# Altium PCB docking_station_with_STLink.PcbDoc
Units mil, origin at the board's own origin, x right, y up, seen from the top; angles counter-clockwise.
Board outline 3937 x 2280 mil, 2 copper layers (Top Layer, Bottom Layer); 53 components, 48 nets, 253 pads, 82 vias.
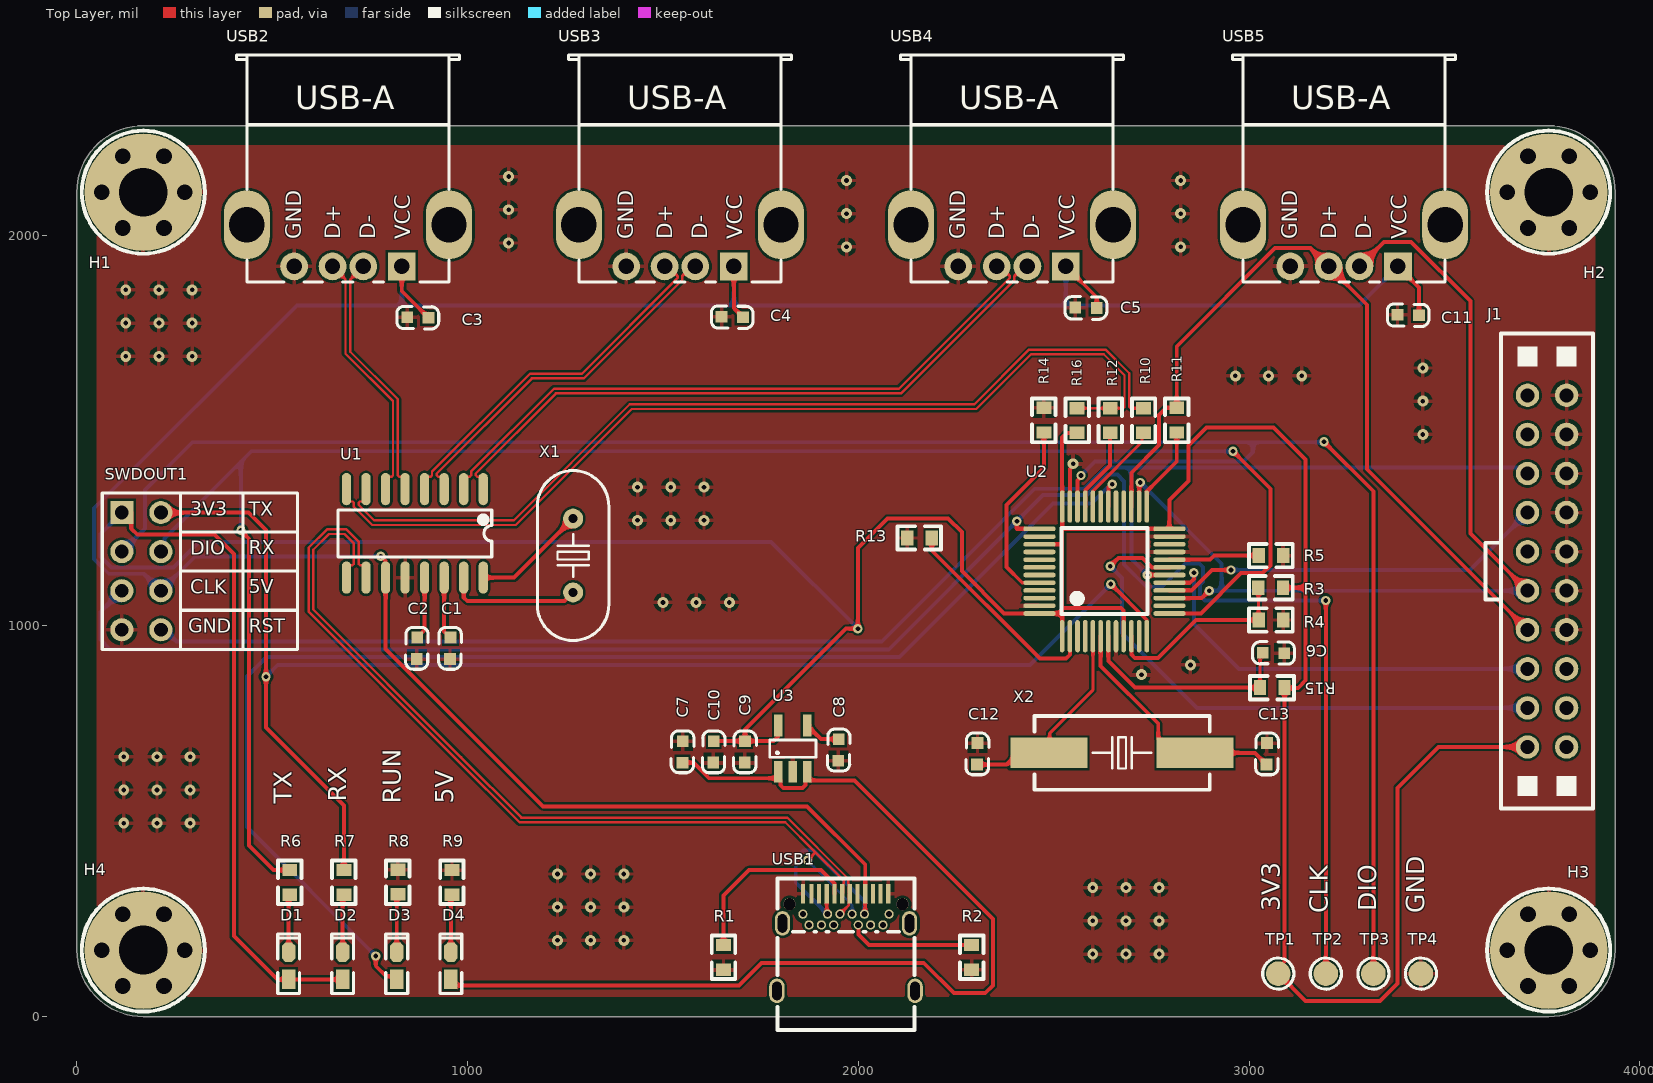
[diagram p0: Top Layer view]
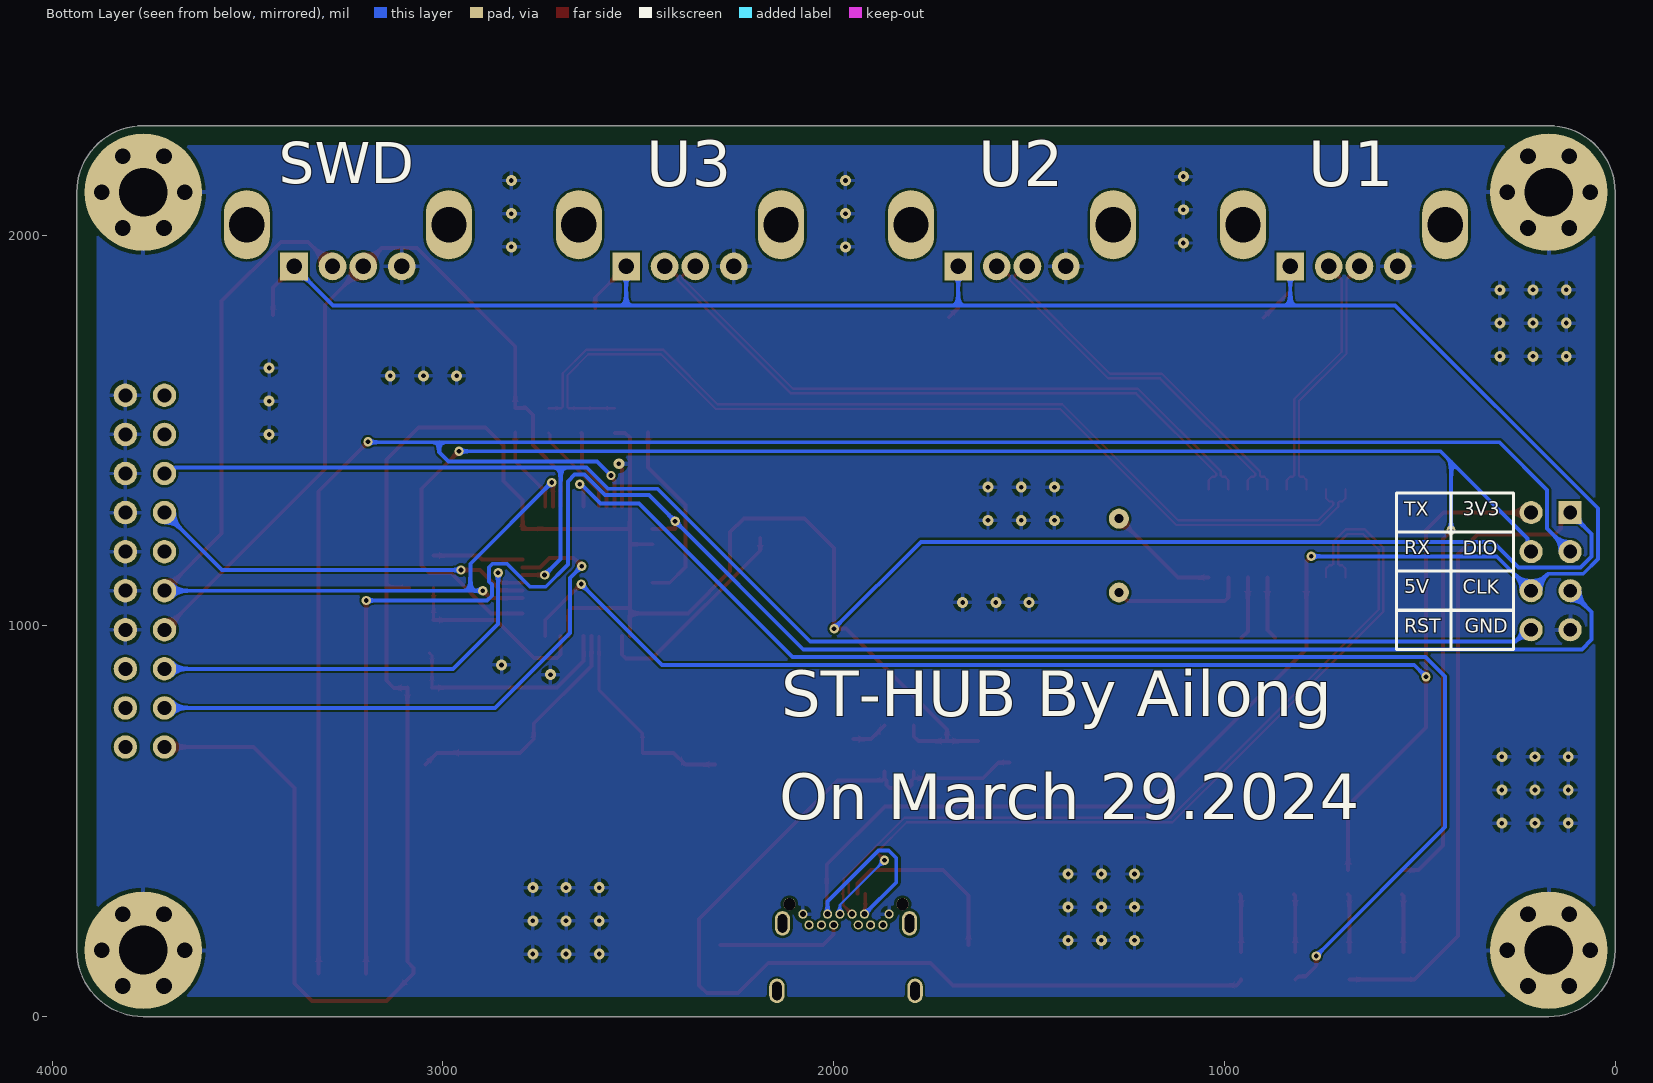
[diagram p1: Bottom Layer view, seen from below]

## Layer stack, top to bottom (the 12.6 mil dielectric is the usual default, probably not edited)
Top Solder: solder mask 0.4, Solder Resist, Dk 3.5
Top Layer: signal copper 1.4
Dielectric 1: dielectric 12.6, FR-4, Dk 4.8
Bottom Layer: signal copper 1.4
Bottom Solder: solder mask 0.4, Solder Resist, Dk 3.5

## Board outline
0,170 0,2110 cw(c170,2110) 170,2280 3767,2280 cw(c3767,2110) 3937,2110 3937,170 cw(c3767,170) 3767,0 170,0 cw(c170,170)

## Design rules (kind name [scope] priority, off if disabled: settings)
BoardOutlineClearance [All] p1: gap=10 ignorepadtopadclearanceinfootprint=FALSE except(0: Arc-SplitContinuation Track-SplitContinuation SMDPad-SplitContinuation THPad-SplitContinuation Via-SplitContinuation Fill-SplitContinuation Poly-SplitContinuation Region-SplitContinuation Text-SplitContinuation; 50: Poly-OutlineEdge)
Clearance [All] p1: gap=6 ignorepadtopadclearanceinfootprint=FALSE
DiffPairsRouting [All] p1: maxlimit=10 minlimit=6 mostfreqgap=6 toplayer_minwidth=6 toplayer_maxwidth=6 toplayer_prefwidth=6 bottomlayer_minwidth=6 bottomlayer_maxwidth=6 bottomlayer_prefwidth=6 maxuncoupledlength=500
HoleSize [All] p1: absolutevalues=TRUE maxlimit=1000 minlimit=1 maxpercent=80.000 minpercent=20.000
MinimumSolderMaskSliver [All] p1: minsoldermaskwidth=0
PolygonConnect [All] p1: connectstyle=Relief reliefconductorwidth=10 reliefentries=4 polygonreliefangle="90 Angle" airgapwidth=10
RoutingVias [All] p1: holewidth=12 width=24 viastyle="Through Hole" minholewidth=10 minwidth=20 maxholewidth=28 maxwidth=50
SilkToSolderMaskClearance [IsPad] p1: minsilkscreentomaskgap=3 clearancetoexposedcopper=TRUE
SolderMaskExpansion [All] p1: expansion=4 istentingtop=FALSE
Width [All] p1: maxlimit=50 minlimit=8 preferedwidth=10
26 further rules are at their usual default settings.

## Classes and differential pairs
differential pair class 90oum: D2 D3 D4 D_D2 D_D3 D_D4 D_UD D_USB UD USB
differential pair D_D2: +D2_N -D2_P
differential pair D_D3: +D3_N -D3_P
differential pair D_D4: +D4_N -D4_P
differential pair D_UD: +UD_N -UD_P
differential pair D_USB: +USB_N -USB_P
differential pair USB: +USB_P -USB_N
differential pair UD: +UD_P -UD_N
differential pair D4: +D4_P -D4_N
differential pair D3: +D3_P -D3_N
differential pair D2: +D2_P -D2_N

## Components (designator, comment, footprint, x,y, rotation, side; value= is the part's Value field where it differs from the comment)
C1 "10UF" 0603C 956.35,970.21 r270 top
C2 "10UF" 0603C 871.35,970.21 r270 top
C3 "100NF" 0603C 845,1790 r0 top
C4 "100NF" 0603C 1649.79,1791.35 r0 top
C5 "100NF" 0603C 2555,1815 r0 top
C6 "0.1uF" 0603C 3090.21,929.65 r180 top value=0.1u
C7 "1uF" 0603C 1551.35,705.21 r270 top
C8 "22nF" 0603C 1948.65,654.79 r90 top
C9 "10uF" 0603C 1708.65,649.85 r90 top
C10 "100nF" 0603C 1628.64,649.85 r90 top
C11 "100NF" 0603C 3379.79,1796.35 r0 top
C12 "20PF" 0603C 2303.65,644.79 r90 top
C13 "20PF" 0603C 3044.65,644.79 r90 top
D1 "color?" "LED 0603B" 542.26,130 r90 top
D2 "color?" "LED 0603B" 680.59,130 r90 top
D3 "color?" "LED 0603B" 818.92,130 r90 top
D4 "color?" "LED 0603B" 957.26,130 r90 top
H1 "固定孔" M3x4+6_N 170,2110 r0 top locked
H2 "固定孔" M3x4+6_N 3767,2110 r0 top locked
H3 "固定孔" M3x4+6_N 3767,170 r0 top locked
H4 "固定孔" M3x4+6_N 170,170 r0 top locked
J1 "JTAG" JLINK 3815,1140 r90 top locked
R1 "5.1K" 0603R 1655,182.99 r270 top value=22R
R2 "5.1K" 0603R 2290,182.99 r270 top value=22R
R3 "10K" 0603R 3087,1097.5 r180 top value=22R
R4 "10K" 0603R 3025,1015 r0 top value=22R
R5 "10K" 0603R 3025,1180 r0 top value=22R
R6 "680R" 0603R 545,375 r270 top value=22R
R7 "680R" 0603R 683.33,375 r270 top value=22R
R8 "2K" 0603R 821.67,313 r90 top value=22R
R9 "680R" 0603R 960,375 r270 top value=22R
R10 "22R" 0603R 2730,1557 r270 top
R11 "100R" 0603R 2815,1495 r90 top value=22R
R12 "22R" 0603R 2645,1557 r270 top
R13 "10K" 0603R 2125,1225 r0 top value=22R
R14 "10K" 0603R 2475,1495 r90 top value=22R
R15 "10K" 0603R 3028,841.97 r0 top value=22R
R16 "1K5" 0603R 2560,1557 r270 top value=22R
SWDOUT1 "HDR2x4_2.54" "Pin HDR2X4/2.54mm-S" 115,1290 r270 top locked
TP1 "TEST" "TEST 1.6" 3075,110 r0 top
TP2 "TEST" "TEST 1.6" 3196.67,110 r0 top
TP3 "TEST" "TEST 1.6" 3318.33,110 r0 top
TP4 "TEST" "TEST 1.6" 3440,110 r0 top
U1 "SL2.1A" SOP16 1040,1350 r270 top
U2 "STM32F103CBT6" "LQFP48 7X7" 2630,1140 r0 top
U3 "RT9193" SOT23-5 1795,626.89 r0 top
USB1 "Type-C" TYPE-C-SMD_TYPE-C-24P-QCHT 1968.5,160 r0 top locked
USB2 "USB-A" USB-A/S_A 831.46,1920 r90 top
USB3 "USB-A" USB-A/S_A 1681.35,1920 r90 top
USB4 "USB-A" USB-A/S_A 2531.24,1920 r90 top
USB5 "USB-A" USB-A/S_A 3381.13,1920 r90 top
X1 "12MHZ" "OSC HC-49S" 1270,1180 r90 top
X2 "8MHZ" "OSC HC-49SMD" 2675,675 r0 top

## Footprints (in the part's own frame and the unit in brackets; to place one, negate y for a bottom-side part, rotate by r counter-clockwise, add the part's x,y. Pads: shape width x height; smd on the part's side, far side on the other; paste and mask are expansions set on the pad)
0603C [mil]
  rect 30x30 smd: 1(0.21,-0.35) 2(55.21,-1.35)
  silkscreen extent -26,-30 81,28, body extent -1,-15 62,17, height 12
0603R [mm]
  rect 0.8x0.965 smd: 1(0,0) 2(1.6,0)
  silkscreen extent -0.64,-0.76 2.21,0.76, body extent -0.04,-0.41 1.56,0.41, height 0.45
JLINK [mil]
  round 60 hole 36 paste+0 mask+2: 1(-450,102.21) 2(-450,2.21) 3(-350,102.21) 4(-350,2.21) 5(-250,102.21) 6(-250,2.21) 7(-150,102.21) 8(-150,2.21) 9(-50,102.21) 10(-50,2.21) 11(50,102.21) 12(50,2.21) 13(150,102.21) 14(150,2.21) 15(250,102.21) 16(250,2.21) 17(350,102.21) 18(350,2.21) 19(450,102.21) 20(450,2.21)
  silkscreen extent -608,-66 608,210
"LED 0603B" [mil] "蓝色0603LED"
  rect 50x35 smd: 1(-35,0.26)
  oct 50x35 smd: 2(35,0.26)
  silkscreen extent -71,-28 81,28, body extent -31,-16 32,16, height 24
"LQFP48 7X7" [mm]
  oval 0.3x2.1 smd: 1(-2.75,-4.227) 2(-2.25,-4.227) 3(-1.75,-4.227) 4(-1.25,-4.227) 5(-0.75,-4.227) 6(-0.25,-4.227) 7(0.25,-4.227) 8(0.75,-4.227) 9(1.25,-4.227) 10(1.75,-4.227) 11(2.25,-4.227) 12(2.75,-4.227) 25(2.75,4.202) 26(2.25,4.202) 27(1.75,4.202) 28(1.25,4.202) 29(0.75,4.202) 30(0.25,4.202) 31(-0.25,4.202) 32(-0.75,4.202) 33(-1.25,4.202) 34(-1.75,4.202) 35(-2.25,4.202) 36(-2.75,4.202)
  oval 2.1x0.3 smd: 13(4.227,-2.75) 14(4.227,-2.25) 15(4.227,-1.75) 16(4.227,-1.25) 17(4.227,-0.75) 18(4.227,-0.25) 19(4.227,0.25) 20(4.227,0.75) 21(4.227,1.25) 22(4.227,1.75) 23(4.227,2.25) 24(4.227,2.75) 37(-4.227,2.75) 38(-4.227,2.25) 39(-4.227,1.75) 40(-4.227,1.25) 41(-4.227,0.75) 42(-4.227,0.25) 43(-4.227,-0.25) 44(-4.227,-0.75) 45(-4.227,-1.25) 46(-4.227,-1.75) 47(-4.227,-2.25) 48(-4.227,-2.75)
  silkscreen extent -2.79,-2.79 2.79,2.79, body extent -4.51,-4.5 4.5,4.5, height 1.45
M3x4+6_N [mil] "M3铜柱，长：4mm，螺纹长：6mm"
  round 40 hole 40: 1(-106,0) 1(-53,-91.8) 1(-53,91.8) 1(53,-91.8) 1(53,91.8) 1(106,0)
  round 300 hole 125: 1(0,0)
  silkscreen extent -157,-157 157,157, body extent -106,-93 106,93, height 159
"OSC HC-49S" [mm]
  round 1.3 hole 0.6: 1(-2.4,0) 2(2.4,0)
  silkscreen extent -5.52,-2.32 5.52,2.33, body extent -5.53,-2.29 5.53,2.36, height 4.13
"OSC HC-49SMD" [mm]
  rect 5x2 smd: 1(-4.75,0) 2(4.75,0)
  silkscreen extent -5.7,-2.4 5.7,2.4, body extent -6.37,-2.41 6.63,2.24, height 4.63
"Pin HDR2X4/2.54mm-S" [mm] "Connector; Header; 4x2 Position"
  rect 1.5x1.5 hole 0.9: 1(0,0)
  round 1.5 hole 0.9: 2(0,2.54) 3(2.54,0) 4(2.54,2.54) 5(5.08,0) 6(5.08,2.54) 7(7.62,0) 8(7.62,2.54)
  silkscreen extent -1.27,-1.27 8.89,3.81, body extent -1.27,-1.27 8.89,3.81, height 7.58
SOP16 [mm]
  oval 2.1x0.6 smd: 1(0,0) 2(0,-1.27) 3(0,-2.54) 4(0,-3.81) 5(0,-5.08) 6(0,-6.35) 7(0,-7.62) 8(0,-8.89) 9(5.75,-8.89) 10(5.75,-7.62) 11(5.75,-6.35) 12(5.75,-5.08) 13(5.75,-3.81) 14(5.75,-2.54) 15(5.75,-1.27) 16(5.75,0)
  silkscreen extent 1.35,-9.44 4.4,0.56, body extent -0.04,-9.45 5.97,0.56, height 1.9
SOT23-5 [mm]
  rect 0.55x1.4 smd: 1(0,0) 2(0.95,0) 3(1.9,0) 4(1.9,3) 5(0,3)
  silkscreen extent -0.55,0.94 2.45,2.06, body extent -0.55,0.27 2.45,3.08, height 1.15
"TEST 1.6" [mm] "测试点1.6mm"
  round 1.6 smd paste-1.6: 1(0,0)
  silkscreen extent -1.01,-1.02 1.02,1.02
TYPE-C-SMD_TYPE-C-24P-QCHT [mm]
  oval 1x1.6 hole 0.6 slot 1.2 at 90 deg: 25(-4.49,-2.395) 25(-4.13,1.995) 25(4.13,1.995) 25(4.49,-2.395)
  rect 0.275x1.25 smd: A1(-2.79,3.92) A2(-2.25,3.92) A3(-1.75,3.92) A4(-1.25,3.92) A5(-0.75,3.92) A6(-0.25,3.92) A7(0.25,3.92) A8(0.75,3.92) A9(1.25,3.92) A10(1.75,3.92) A11(2.25,3.92) A12(2.75,3.92)
  round 0.6 hole 0.4: B1(2.8,2.595) B2(2.4,1.895) B3(1.6,1.895) B4(1.2,2.595) B5(0.8,1.895) B6(0.4,2.595) B7(-0.4,2.595) B8(-0.8,1.895) B9(-1.2,2.595) B10(-1.6,1.895) B11(-2.4,1.895) B12(-2.8,2.595)
  round 0.8 hole 0.8 unplated: ""(-3.675,3.246) ""(3.675,3.246)
  silkscreen extent -4.46,-4.93 4.46,4.93
USB-A/S_A [mm]
  oval 4.5x3 hole 2.3: 0(2.71,10.07) 0(2.71,-3.07)
  rect 1.8x1.8 hole 1: 1(0,0)
  round 1.8 hole 1: 2(0,2.5) 3(0,4.5) 4(0,7)
  silkscreen extent -1.01,-3.75 13.75,10.75, body extent -0.55,-3.81 13.76,10.87, height 6.8

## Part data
C1 C2 C3 C4 C5 C7 C8 C9 C10 C11 C12 C13: library part CAP, "无极性电容"
C6: library part 电容-0402, "Capacitor"
D1 D2 D3 D4: library part LED_0402, "LED"
J1: library part "Pin HDR2X10"
R1 R2 R3 R4 R5 R6 R7 R8 R9 R10 R11 R12 R13 R14 R15 R16: library part 电阻-0402, "Resistor"
SWDOUT1: "Header"
TP1 TP2 TP3 TP4: "测试点"
U1: "USB2.0扩展"
U2: "ARM Cortex-M3 32-bit MCU, 128 KB Flash, 20 KB Internal RAM, 37 I/Os, 48-pin LQFP, -40 to 85 degC, Tray", I/Os (High Current)=37, Operating Frequency(F) (Processor speed) (MHz)=72, Supplier Part Number 1=497-6288-ND, Supply Voltage(Vcc) min (V)=2
U3: library part RT9193X_5P, ICA_MFR_NAME=RICHTEK, ICA_PARTNUM=$$2191094$$RT9193-15CU5, Part Number=TMP-13
USB1: library part USB-Type-C-TOP
X1 X2: library part XTAL-2P, "2脚无源脚晶振"

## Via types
v1: diameter 28, hole 12, Top Layer to Bottom Layer, tented both sides, 63 vias
v2: diameter 24, hole 12, Top Layer to Bottom Layer, tented both sides, 19 vias

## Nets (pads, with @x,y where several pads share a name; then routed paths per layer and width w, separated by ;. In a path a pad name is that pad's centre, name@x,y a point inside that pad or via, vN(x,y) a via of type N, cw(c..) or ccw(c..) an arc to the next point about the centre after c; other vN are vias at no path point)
3V3: C9.2 C10.2 D1.1 D2.1 J1.1 R3.1 R15.2 R16.2 SWDOUT1.1 TP1.1 U2.1 U2.9 U2.24 U2.36 U2.39 U2.48 U3.5 | length 9749.7
  Top Layer w10: SWDOUT1.1 139.53,1290 139.53,1248.37 154.43,1233.47 352.53,1233.47 402,1184 402,206 513,95 D1.1 D2.1 ; C10.2 C9.2 ; U3.5 1795,717.06 1783,705.06 C9.2 ; U2.39 2520.63,1208.9 2521.73,1210 ; U2.1 2521.73,1031.73 ; 2525,1046 2673,1046 2679.21,1039.79 U2.9 ; 2526,1248.27 U2.24@2796,1248.27 ; R16.2 2534.01,1494.01 2521.73,1481.73 U2.36 2521.73,1210 ; U2.24 U2.24@2796,1248.27 ; R3.1 3145,1097.5 ; R15.2 R15.2@3090.99,841 ; J1.1 3485,690 3380,585 3380,85 3335,40 3145,40 TP1.1 3075,124.34 3090.99,140.33 R15.2@3090.99,841 ; C9.2 1710,735 1968,993 v2(1999,993) 1999,1199 2075,1275 2230,1275 2265,1240 2265,1140 2373.27,1031.73 U2.48 2521.73,1031.73 ; 2521.73,1031.73 2521.73,1210 ; U2.24@2796,1248.27 2796,1322 2845,1371 2845,1462 2891,1508 3063,1508 3145,1426 3145,1097.5 ; R15.2@3090.99,841 3126,841 3145,860 3145,1097.5
  Bottom Layer w10: SWDOUT1.1 60,1235 60,1177.63 88.16,1149.47 247.47,1149.47 313,1215 1777,1215 v2(1999,993)
5V: C3.2 C4.2 C5.2 C11.2 SWDOUT1.6 U1.11 USB1.A4 USB1.A9 USB1.B4 USB1.B9 USB2.1 USB3.1 USB4.1 USB5.1 | length 7735.1
  Top Layer w8: USB1.A4 1919.28,264.15 USB1.B9 ; USB1.B4 2017.71,264.14 USB1.A9
  Top Layer w10: v2(778,1178) 790,1166 U1.11 790,941 1193,538 1869.16,538 2017.71,389.44 USB1.A9 ; USB2.1 831.46,1857.4 C3.2 ; USB3.1 1681.35,1813.65 C4.2 ; USB4.1 2610.21,1841.03 C5.2 ; USB5.1 3435,1866.13 C11.2
  Bottom Layer w10: v2(778,1178) 303,1178 SWDOUT1.6 171.53,1133.47 81.53,1133.47 44,1171 44,1301 563,1820 831.46,1820 ; USB2.1 831.46,1820 ; USB3.1 1681.35,1820 ; USB1.B9 1840,343.43 1840,406 1859,425 1885,425 2015.74,294.26 USB1.B4 ; USB4.1@2531.24,1915 2531.24,1820 ; USB5.1 3281.13,1820 2531.24,1820 ; 831.46,1820 1681.35,1820 ; 1681.35,1820 2531.24,1820
+5: C7.2 D4.1 U3.1 U3.3 | length 2659.2
  Top Layer w10: D4.1 957,92.5 969.5,80 1695,80 1752.5,137.5 2167.5,137.5 2245,60 2325,60 2345,80 2345,250 1990.67,604.33 1875.63,604.33 U3.3@1869.8,610.16 ; C7.2 1578,650 1618,610 U3.1@1795,610 ; U3.1 U3.1@1795,610 ; U3.3 U3.3@1869.8,610.16 ; U3.1@1795,610 1800.35,604.65 1800.35,592.65 1808,585 1856.8,585 1864.45,592.65 1864.45,604.8 U3.3@1869.8,610.16
D2_N: U1.5 USB2.2 | length 646.3
  Top Layer w6: USB2.2 699.66,1886.63 699.66,1701.67 821,1580.33 821,1384.99 824.51,1381.47 831.86,1381.47 840,1373.33 U1.5
D2_P: U1.6 USB2.3 | length 646.3
  Top Layer w6: USB2.3 687.66,1886.63 687.66,1696.7 809,1575.36 809,1384.99 805.49,1381.47 798.14,1381.47 790,1373.33 U1.6
D3_N: U1.3 USB3.2 | length 939.4
  Top Layer w6: U1.3 940,1373.33 931.86,1381.47 924.51,1381.47 921,1384.99 921,1389.96 1164.56,1633.52 1297.51,1633.52 1549.55,1885.56 1549.55,1895.5 1574.05,1920 USB3.2
D3_P: U1.4 USB3.3 | length 939.4
  Top Layer w6: U1.4 890,1373.33 898.14,1381.47 905.49,1381.47 909,1384.99 909,1394.93 1159.59,1645.52 1292.54,1645.52 1537.55,1890.53 1537.55,1895.5 1513.06,1920 USB3.3
D4_N: U1.1 USB4.2 | length 1689.3
  Top Layer w6: U1.1 1040,1373.33 1031.86,1381.47 1024.51,1381.47 1021,1384.99 1021,1389.96 1226.04,1595 2108.88,1595 2399.45,1885.56 2399.45,1895.5 2423.94,1920 USB4.2
D4_P: U1.2 USB4.3 | length 1689.3
  Top Layer w6: U1.2 990,1373.33 998.14,1381.47 1005.49,1381.47 1009,1384.99 1009,1394.93 1221.07,1607 2103.91,1607 2387.45,1890.53 2387.45,1895.5 2362.95,1920 USB4.3
GND: C1.2 C2.2 C3.1 C4.1 C5.1 C6.1 C7.1 C8.1 C9.1 C10.1 C11.1 C12.2 C13.2 H1.1 H2.1 H3.1 H4.1 J1.8 J1.10 J1.12 J1.14 J1.16 J1.18 J1.20 R1.2 R2.2 R4.2 R5.2 R8.2 R9.1 R13.1 R14.2 SWDOUT1.7 TP4.1 U1.12 U2.8 U2.21 U2.23 U2.35 U2.47 U3.2 USB1.A1 USB1.A12 USB1.B1 USB1.B12 USB2.4 USB3.4 USB4.4 USB5.4 | length 113.1
  Top Layer w10: U2.35 2541.42,1401.55 2550,1410.13 v1(2550,1415)
  other v1: 2600,160 2685,160 2770,160 1230,195 1315,195 1400,195 2600,245 2685,245 2770,245 1230,280 1315,280 1400,280 2600,330 2685,330 2770,330 1230,365 1315,365 1400,365 120,495 205,495 290,495 120,580 205,580 290,580 120,665 205,665 290,665 2725,875 2850,900 1500,1060 1585,1060 1670,1060 1435,1270 1520,1270 1605,1270 1435,1355 1520,1355 1605,1355 3445,1490 3445,1575 2965,1640 3050,1640 3135,1640 3445,1660 125,1690 210,1690 295,1690 125,1775 210,1775 295,1775 125,1860 210,1860 295,1860 1970,1970 2825,1970 1105,1980 1970,2055 2825,2055 1105,2065 1970,2140 2825,2140 1105,2150
JTCK: J1.9 U2.15 U2.26 USB5.2 | length 2525.1
  Top Layer w10: U2.26 2718.58,1363.58 v2(2722,1367) ; U2.15 2879.1,1071.1 v2(2898,1090) ; USB5.2 3345.71,1983 3415,1983 3566.5,1831.5 3566.5,1236.29 J1.9
  Bottom Layer w10: v2(2722,1367) 2930,1159 2930,1090 ; v2(2898,1090) 2930,1090 ; J1.9 2930,1090
JTDI: J1.5 U2.17 | length 1114.9
  Top Layer w10: U2.17 2849.47,1110.47 2859,1120 v2(2859,1136)
  Bottom Layer w10: v2(2859,1136) 2859,1005 2974,890 J1.5
JTDO: J1.13 U2.16 | length 998.9
  Top Layer w10: U2.16 2852.79,1090.79 2905,1143 v2(2954,1143)
  Bottom Layer w10: v2(2954,1143) 3565.79,1143 J1.13
JTMS: J1.7 R11.2 U2.27 USB5.3 | length 2127.1
  Top Layer w10: U2.27 2698.9,1391.85 2770,1462.95 2770,1540 2787.99,1557.99 R11.2 2815,1715 3067,1967 3156.97,1967 USB5.3 3301.97,1822 3301.97,1400.82 J1.7
LED_RUN: D3.1 U2.30 | length 3427.8
  Top Layer w10: v2(765,155) 765,130 792.02,102.98 810.69,102.98 D3.1 ; U2.30 2639.84,1355.84 2646.85,1362.85 v2(2650.18,1362.85)
  Bottom Layer w10: v2(765,155) 435,485 435,870 485,920 2105,920 2498,1313 2597,1313 2646.85,1362.85 v2(2650.18,1362.85)
NetC1_1: C1.1 U1.14 | length 160.2
  Top Layer w10: U1.14 940,986 C1.1
NetC2_1: C2.1 U1.13 | length 161.5
  Top Layer w10: C2.1 890,989 U1.13
NetC6_2: C6.2 R15.1 U2.7 | length 571.8
  Top Layer w8: R15.1 3028,924 C6.2
  Top Layer w10: U2.7 2639.84,910.16 2708.03,841.97 R15.1
NetC8_2: C8.2 U3.4 | length 94.7
  Top Layer w10: U3.4 1904.8,710 C8.2
NetC12_1: C12.1 U2.5 X2.1 | length 541.6
  Top Layer w8: X2.1 2489.75,676.76 2489.75,724.75 2600.47,835.47 U2.5
  Top Layer w10: C12.1 2380,645 2410,675 X2.1
NetC13_1: C13.1 U2.6 X2.2 | length 628.8
  Top Layer w10: U2.6 2620.16,897.09 2767.58,749.67 2767.58,710.37 2802.95,675 X2.2 3015,675 C13.1
NetD1_2: D1.2 R6.2 | length 148.2
  Top Layer w10: D1.2 542,309.01 R6.2
NetD2_2: D2.2 R7.2 | length 148.2
  Top Layer w10: D2.2 680.33,309.01 R7.2
NetD3_2: D3.2 R8.1 | length 149.2
  Top Layer w10: D3.2 818.67,310 R8.1
NetD4_2: D4.2 R9.2 | length 148.2
  Top Layer w10: D4.2 957,309.01 R9.2
NetR1_1: R1.1 USB1.A5 | length 478.2
  Top Layer w10: R1.1 1655,310 1720,375 1904.19,375 1938.56,340.63 1938.56,314.74 USB1.A5
NetR2_1: R2.1 USB1.B5 | length 325.8
  Top Layer w10: USB1.B5 2000,210 2027.01,182.99 R2.1
NetR3_2: R3.2 R4.1 U2.10 | length 499.7
  Top Layer w8: R3.2 3024.01,1015.99 R4.1
  Top Layer w10: U2.10 2698.9,926.62 2707.51,918 2767.17,918 2864.17,1015 R4.1
NetR5_1: R5.1 U2.20 | length 232.9
  Top Layer w10: U2.20 2900.53,1169.53 2911,1180 R5.1
NetR10_2: R10.2 U2.32 | length 242.2
  Top Layer w8: U2.32 2601.2,1306.15 2601.2,1346.2 2725.95,1470.95 2725.95,1489.95 R10.2
NetR11_1: R11.1 U2.25 | length 221.4
  Top Layer w10: U2.25 2738.27,1344.4 2815,1421.13 R11.1
NetR12_2: R12.2 U2.33 | length 215.2
  Top Layer w10: U2.33 2581.13,1305.76 2581.13,1347.35 2644.12,1410.33 2644.12,1493.13 R12.2
NetR13_2: R13.2 U2.2 | length 551.5
  Top Layer w10: R13.2 2187.99,1193.03 2464.6,916.42 2531.84,916.42 2541.42,926 U2.2
NetR14_1: R14.1 U2.44 | length 484.7
  Top Layer w10: U2.44 2419.68,1110.47 2379.37,1150.78 2379.37,1309.37 2475,1405 R14.1
NetU1_15: U1.15 X1.1 | length 343.3
  Top Layer w10: U1.15 990,1073 999,1064 1248.49,1064 X1.1
NetU1_16: U1.16 X1.2 | length 292.5
  Top Layer w10: U1.16 1119.13,1123.62 X1.2
nRST: J1.15 SWDOUT1.8 U2.18 | length 4049
  Top Layer w10: v2(2740,1130.16) U2.18
  Bottom Layer w10: SWDOUT1.8 224.69,990 254.69,960 2060,960 2451,1351 2578,1351 2632,1405 2699,1405 ; v2(2740,1130.16) 2699,1171.16 2699,1405 ; J1.15 3699.26,1390 3684.26,1405 2699,1405
RENUMn: U2.38
RX: R6.1 SWDOUT1.4 U2.13 | length 4627.3
  Top Layer w10: v2@419,1244 440,1223 440,438 503,375 R6.1 ; U2.13 2876.73,1031.73 2980,1135 3035,1135 3055,1155 3055,1351 v2(2959,1447)
  Bottom Layer w10: SWDOUT1.4 223.99,1198.99 223.99,1223.99 420,1420 ; v2(420,1245) 420,1420 ; v2(2959,1447) 447,1447 420,1420
ST_SWCLK: SWDOUT1.5 TP2.1 U2.37 | length 4871.7
  Top Layer w10: v2(2406,1268) 2406,1248.27 U2.37 ; TP2.1 v2(3196.67,1065)
  Bottom Layer w10: SWDOUT1.5 60,1035 60,965 85,940 2078,940 v2(2406,1268) 2472.5,1334.5 2585.5,1334.5 2638,1387 2663,1387 2680,1370 2680,1157.13 2736.98,1100.16 2777.16,1100.16 2836,1159 2873,1159 2882,1150 2882,1113 2875,1106 2875,1077 2887,1065 v2(3196.67,1065)
ST_SWDIO: SWDOUT1.3 TP3.1 U2.34 | length 5237.4
  Top Layer w10: U2.34 2561.1,1372.31 2570,1381.21 v2(2570,1385) ; v2(3192,1471) 3318.33,1344.67 TP3.1
  Bottom Layer w10: SWDOUT1.3 174,1249 174,1348 296,1470 3010,1470 ; v2(2570,1385) 2606,1421 2986,1421 3010,1445 3010,1470 ; v2@3192,1470 3010,1470
T_SWO: U2.31
TRST: J1.3 U2.19 | length 1471
  Top Layer w10: v2(2644.84,1153) 2665.84,1174 2727.84,1174 2752,1149.84 U2.19
  Bottom Layer w10: v2(2644.84,1153) 2675.13,1122.71 2675.13,982 2867.13,790 J1.3
TX: R7.1 SWDOUT1.2 U2.12 | length 3672.2
  Top Layer w10: SWDOUT1.2 439,1290 484,1245 v2(484,870) 484,740 683.33,540.67 R7.1 ; v2(2646.27,1107) 2738.27,1015 U2.12
  Bottom Layer w10: v2(484,870) 514,900 2439.27,900 v2(2646.27,1107)
UD_N: U1.9 USB1.A7 USB1.B7 | length 2140.9
  Top Layer w6: U1.9 690,1146.96 698.14,1155.1 705.49,1155.1 709,1158.61 709,1211 685,1235 645,1235 605,1195 605,1041.97 983.49,663.49 1137.74,509.23 1818.18,509.23 1974.5,352.91 1974.5,339.45 1975.93,338.02 1975.93,316.74 USB1.A7 1975.93,311.92 1975.93,285.34 USB1.B7
UD_P: U1.10 USB1.A6 USB1.B6 | length 2333.1
  Top Layer w6: U1.10 740,1146.96 731.86,1155.1 724.51,1155.1 721,1158.61 721,1215.97 689.97,1247 640.03,1247 593,1199.97 593,1037 966.51,663.49 1132.77,497.23 1813.21,497.23 1887.85,422.58 ; v2(1870,400) 1887.85,417.85 1887.85,422.58 ; USB1.A6 1961.07,316.74 1961.07,338.02 1962.5,339.45 1962.5,347.94 1887.85,422.58
  Bottom Layer w6: v2(1870,400) 1984.25,285.75 USB1.B6
USB_N: R10.1 U1.7 | length 2371.2
  Top Layer w6: U1.7 740,1326.67 731.86,1318.53 724.51,1318.53 721,1315.01 721,1310.04 761.04,1270 1118.23,1270 1415.23,1567 2297,1567 2437,1707 2633,1707 2693.5,1646.5 2693.5,1560.51 2697.01,1557 R10.1
USB_P: R12.1 R16.1 U1.8 | length 2456.2
  Top Layer w6: U1.8 690,1326.67 698.14,1318.53 705.49,1318.53 709,1315.01 709,1305.07 756.07,1258 1123.2,1258 1420.2,1555 2301.97,1555 2441.97,1695 2628.03,1695 2681.5,1641.53 2681.5,1560.51 2677.99,1557 R12.1 R16.1
pads on no net: J1.2 J1.4 J1.6 J1.11 J1.17 J1.19 U2.3 U2.4 U2.11 U2.14 U2.22 U2.28 U2.29 U2.40 U2.41 U2.42 U2.43 U2.45 U2.46 USB1. USB1.25 USB1.A2 USB1.A3 USB1.A8 USB1.A10 USB1.A11 USB1.B2 USB1.B3 USB1.B8 USB1.B10 USB1.B11 USB2.0 USB3.0 USB4.0 USB5.0

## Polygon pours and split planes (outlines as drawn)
GND on Bottom Layer "GND_L02_P002" (solid, remove dead copper, pour order 2): 0,170 0,2110 cw(c170,2110) 170,2280 3767,2280 cw(c3767,2110) 3937,2110 3937,170 cw(c3767,170) 3767,0 170,0 cw(c170,170)
GND on Top Layer "GND_L01_P001" (solid, remove dead copper, pour order 1): 0,170 0,2110 cw(c170,2110) 170,2280 3767,2280 cw(c3767,2110) 3937,2110 3937,170 cw(c3767,170) 3767,0 170,0 cw(c170,170)

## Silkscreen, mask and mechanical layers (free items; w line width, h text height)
Top Overlay:
  lines w8: 265,940 565,940 565,1340 265,1340 ; 265,1040 560,1040 ; 265,1140 565,1140 ; 265,1240 565,1240 ; 425,940 425,1340
  text "3V3" at 290,1270.67 h60
  text "TX" at 440,1270.83 h60
  text "DIO" at 290,1170.67 h60
  text "RX" at 440,1171.44 h60
  text "CLK" at 290,1070.67 h60
  text "5V" at 440,1071.39 h60
  text "GND" at 285,970.67 h60
  text "RST" at 440,970.67 h60
  text "RX" at 705,550 h80 r90
  text "TX" at 565,545 h80 r90
  text "RUN" at 844.11,545 h80 r90
  text "5V" at 979.11,545 h80 r90
  text "3V3" at 3094.11,270 h80 r90
  text "DIO" at 3340.78,270 h80 r90
  text "CLK" at 3217.45,265 h80 r90
  text "GND" at 3464.11,265 h80 r90
Bottom Overlay:
  lines w8: 260,1040 555,1040 ; 260,1140 560,1140 ; 260,1240 560,1240 ; 420,940 420,1340 ; 260,940 260,1340 560,1340 560,940 260,940
  text "SWD" at 3420,2098.58 h180
  text "U1" at 785,2087.22 h200
  text "U2" at 1630,2087.22 h200
  text "U3" at 2480,2087.22 h200
  text "3V3" at 390,1270.67 h60
  text "TX" at 540,1270.83 h60
  text "DIO" at 390,1170.67 h60
  text "RX" at 540,1171.44 h60
  text "CLK" at 390,1070.67 h60
  text "5V" at 540,1071.39 h60
  text "GND" at 385,970.67 h60
  text "RST" at 540,970.67 h60
  text "ST-HUB By Ailong" at 2134.81,730.17 h200
  text "On March 29.2024" at 2139.81,466.11 h200
Mechanical 1:
  the board outline again, w10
